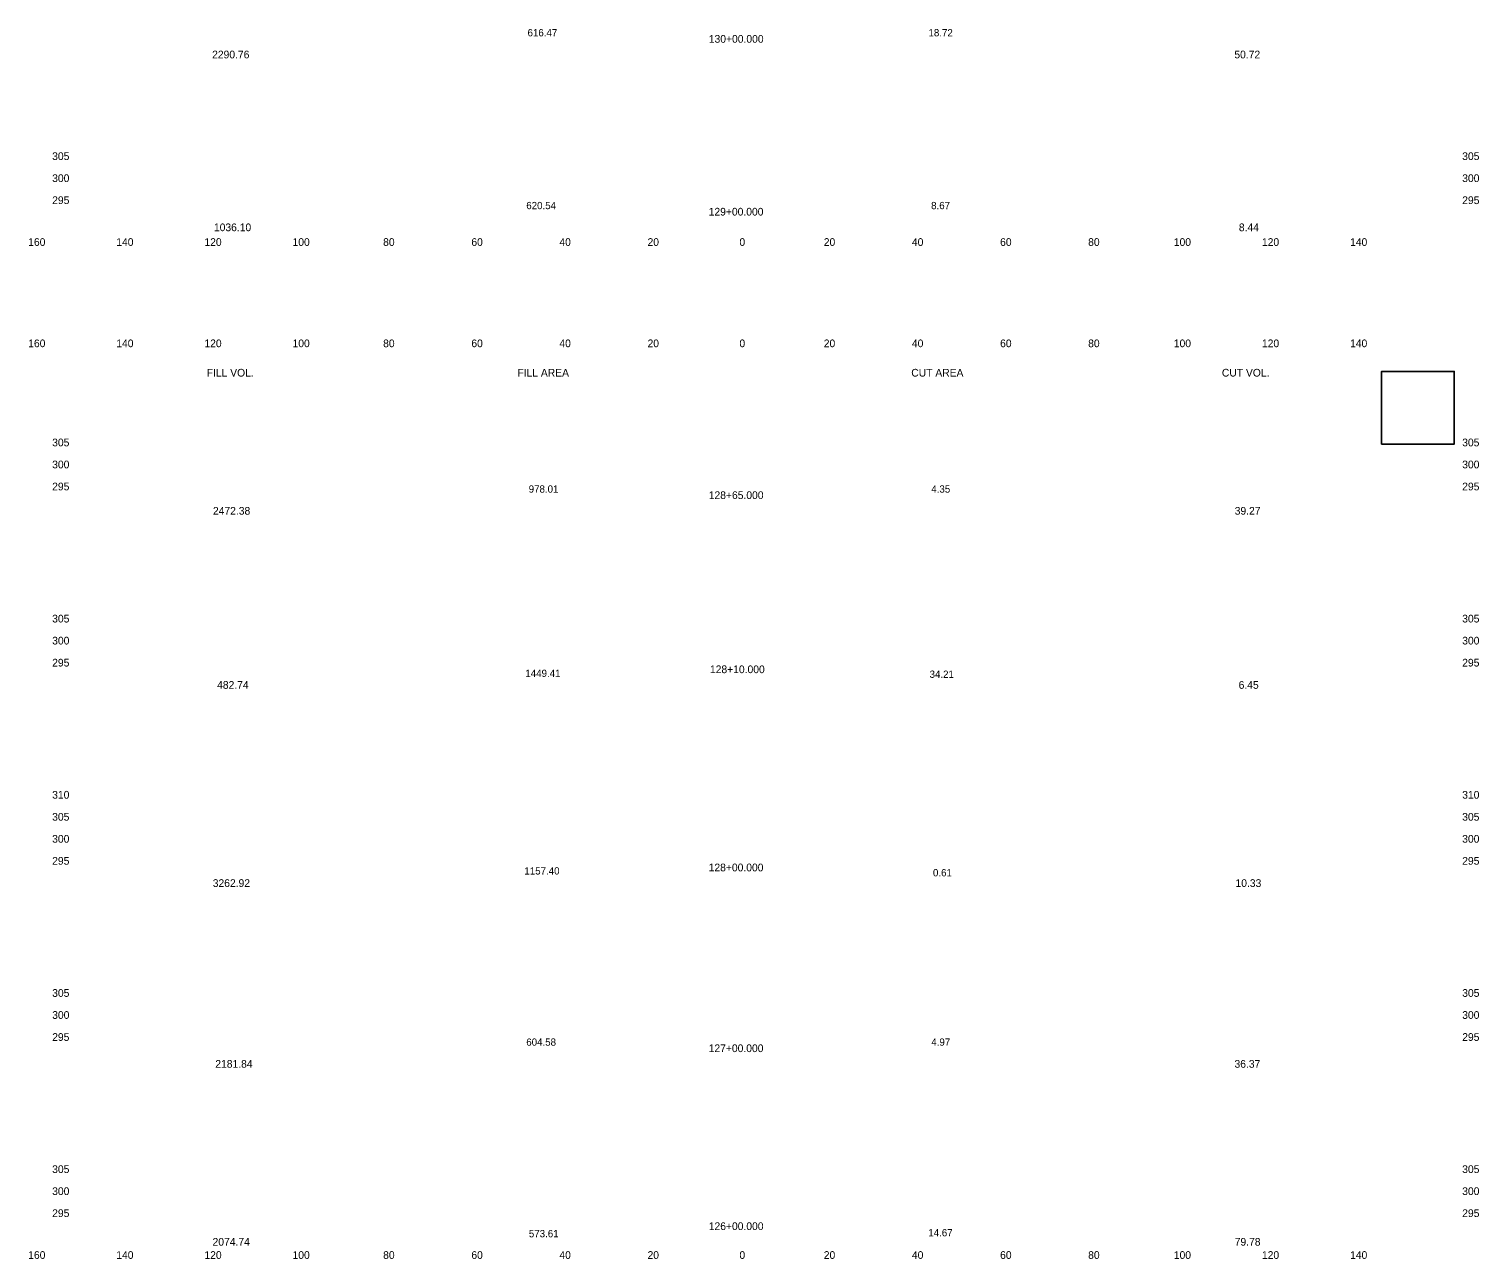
# Model space of a CAD drawing. Extents: x 21477 to 21806, y 6470 to 11049.
# Drawn here: x 21477.1 to 21806.1, y 8770.3 to 9049.6 of the extents above; entities that cross this region are included whole.
import ezdxf

# ---------------------------------------------------------------- set-up
doc = ezdxf.new("R2010")
doc.units = 0
for name, color, linetype in [('SHEET_CONSULTANT_STAMP', 7, 'Continuous'), ('XS_SHEET_EW_TX_AREA', 7, 'Continuous'), ('XS_SHEET_EW_TX_VOLUME', 7, 'Continuous'), ('XS_SHEET_LABELS_ELEVATION', 7, 'Continuous'), ('XS_SHEET_LABELS_OFFSET', 7, 'Continuous'), ('XS_SHEET_LABELS_STATION', 7, 'Continuous'), ('XS_SHEET_TX', 7, 'Continuous')]:
    doc.layers.add(name, color=color, linetype=linetype)

msp = doc.modelspace()

# ---------------------------------------------------------------- linework, layer by layer
at = {"layer": 'SHEET_CONSULTANT_STAMP'}
msp.add_lwpolyline([(21784.04, 8955.34), (21800.54, 8955.34), (21800.54, 8971.84), (21784.04, 8971.84)], close=True, dxfattribs=at)

# ---------------------------------------------------------------- texts
at = {"layer": 'XS_SHEET_EW_TX_AREA'}
for s, p in [(' 616.47 ', (21589.61, 9047.92)), (' 18.72 ', (21680.6, 9047.92)), (' 620.54 ', (21589.32, 9008.68)), (' 8.67 ', (21681.2, 9008.68)), (' 978.01 ', (21589.87, 8944.32)), (' 4.35 ', (21681.24, 8944.32)), (' 1449.41 ', (21589.11, 8902.46)), (' 34.21 ', (21680.85, 8902.27)), (' 1157.40 ', (21588.89, 8857.61)), (' 0.61 ', (21681.62, 8857.2)), (' 604.58 ', (21589.32, 8818.74)), (' 4.97 ', (21681.24, 8818.74)), (' 573.61 ', (21589.91, 8775.25)), (' 14.67 ', (21680.55, 8775.45))]:
    msp.add_text(s, height=1.65, dxfattribs=at).set_placement(p)
at = {"layer": 'XS_SHEET_EW_TX_VOLUME'}
for s, p in [(' 2290.76 ', (21517.99, 9042.92)), (' 50.72 ', (21749.98, 9042.92)), (' 1036.10 ', (21518.4, 9003.68)), (' 8.44 ', (21751, 9003.68)), (' 2472.38 ', (21518.18, 8939.32)), (' 39.27 ', (21750.06, 8939.32)), (' 482.74 ', (21519.12, 8899.78)), (' 6.45 ', (21750.95, 8899.78)), (' 3262.92 ', (21518.13, 8854.79)), (' 10.33 ', (21750.24, 8854.79)), (' 2181.84 ', (21518.71, 8813.74)), (' 36.37 ', (21750.01, 8813.74)), (' 2074.74 ', (21518.09, 8773.34)), (' 79.78 ', (21750.06, 8773.34))]:
    msp.add_text(s, height=1.75, dxfattribs=at).set_placement(p)
at = {"layer": 'XS_SHEET_LABELS_ELEVATION'}
for s, p in [('  305  ', (21481.04, 9019.84)), ('  305  ', (21801.04, 9019.84)), ('  300  ', (21481.04, 9014.84)), ('  300  ', (21801.04, 9014.84)), ('  295  ', (21481.04, 9009.84)), ('  295  ', (21801.04, 9009.84)), ('  305  ', (21481.04, 8954.84)), ('  305  ', (21801.04, 8954.84)), ('  300  ', (21481.04, 8949.84)), ('  300  ', (21801.04, 8949.84)), ('  295  ', (21481.04, 8944.84)), ('  295  ', (21801.04, 8944.84)), ('  305  ', (21481.04, 8914.84)), ('  305  ', (21801.04, 8914.84)), ('  300  ', (21481.04, 8909.84)), ('  300  ', (21801.04, 8909.84)), ('  295  ', (21481.04, 8904.84)), ('  295  ', (21801.04, 8904.84)), ('  310  ', (21481.04, 8874.84)), ('  310  ', (21801.04, 8874.84)), ('  305  ', (21481.04, 8869.84)), ('  305  ', (21801.04, 8869.84)), ('  300  ', (21481.04, 8864.84)), ('  300  ', (21801.04, 8864.84)), ('  295  ', (21481.04, 8859.84)), ('  295  ', (21801.04, 8859.84)), ('  305  ', (21481.04, 8829.84)), ('  305  ', (21801.04, 8829.84)), ('  300  ', (21481.04, 8824.84)), ('  300  ', (21801.04, 8824.84)), ('  295  ', (21481.04, 8819.84)), ('  295  ', (21801.04, 8819.84)), ('  305  ', (21481.04, 8789.84)), ('  305  ', (21801.04, 8789.84)), ('  300  ', (21481.04, 8784.84)), ('  300  ', (21801.04, 8784.84)), ('  295  ', (21481.04, 8779.84)), ('  295  ', (21801.04, 8779.84))]:
    msp.add_text(s, height=1.75, dxfattribs=at).set_placement(p)
at = {"layer": 'XS_SHEET_LABELS_OFFSET'}
for s, p in [('  160  ', (21475.6, 9000.34)), ('  140  ', (21495.59, 9000.34)), ('  120  ', (21515.59, 9000.34)), ('  100  ', (21535.59, 9000.34)), ('  80  ', (21556.15, 9000.34)), ('  60  ', (21576.17, 9000.34)), ('  40  ', (21596.15, 9000.34)), ('  20  ', (21616.15, 9000.34)), ('  0  ', (21637.01, 9000.34)), ('  0  ', (21637.01, 9000.34)), ('  20  ', (21656.15, 9000.34)), ('  40  ', (21676.15, 9000.34)), ('  60  ', (21696.17, 9000.34)), ('  80  ', (21716.15, 9000.34)), ('  100  ', (21735.59, 9000.34)), ('  120  ', (21755.59, 9000.34)), ('  140  ', (21775.59, 9000.34)), ('  160  ', (21475.6, 8977.34)), ('  140  ', (21495.59, 8977.34)), ('  120  ', (21515.59, 8977.34)), ('  100  ', (21535.59, 8977.34)), ('  80  ', (21556.15, 8977.34)), ('  60  ', (21576.17, 8977.34)), ('  40  ', (21596.15, 8977.34)), ('  20  ', (21616.15, 8977.34)), ('  0  ', (21637.01, 8977.34)), ('  0  ', (21637.01, 8977.34)), ('  20  ', (21656.15, 8977.34)), ('  40  ', (21676.15, 8977.34)), ('  60  ', (21696.17, 8977.34)), ('  80  ', (21716.15, 8977.34)), ('  100  ', (21735.59, 8977.34)), ('  120  ', (21755.59, 8977.34)), ('  140  ', (21775.59, 8977.34)), ('  160  ', (21475.6, 8770.34)), ('  140  ', (21495.59, 8770.34)), ('  120  ', (21515.59, 8770.34)), ('  100  ', (21535.59, 8770.34)), ('  80  ', (21556.15, 8770.34)), ('  60  ', (21576.17, 8770.34)), ('  40  ', (21596.15, 8770.34)), ('  20  ', (21616.15, 8770.34)), ('  0  ', (21637.01, 8770.34)), ('  0  ', (21637.01, 8770.34)), ('  20  ', (21656.15, 8770.34)), ('  40  ', (21676.15, 8770.34)), ('  60  ', (21696.17, 8770.34)), ('  80  ', (21716.15, 8770.34)), ('  100  ', (21735.59, 8770.34)), ('  120  ', (21755.59, 8770.34)), ('  140  ', (21775.59, 8770.34))]:
    msp.add_text(s, height=1.75, dxfattribs=at).set_placement(p)
at = {"layer": 'XS_SHEET_LABELS_STATION'}
for s, p in [('  130+00.000  ', (21630.06, 9046.47)), ('  129+00.000  ', (21630.03, 9007.23)), ('  128+65.000  ', (21630.05, 8942.87)), ('  128+10.000  ', (21630.32, 8903.33)), ('  128+00.000  ', (21630.03, 8858.34)), ('  127+00.000  ', (21630.03, 8817.29)), ('  126+00.000  ', (21630.05, 8776.89))]:
    msp.add_text(s, height=1.75, dxfattribs=at).set_placement(p)
at = {"layer": 'XS_SHEET_TX'}
for s, p in [('FILL VOL.', (21517.41, 8970.67)), ('FILL AREA', (21587.92, 8970.67)), ('CUT AREA', (21677.31, 8970.67)), ('CUT VOL.', (21747.8, 8970.67))]:
    msp.add_text(s, height=1.75, dxfattribs=at).set_placement(p)

doc.saveas('drawing.dxf')
